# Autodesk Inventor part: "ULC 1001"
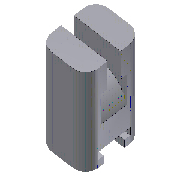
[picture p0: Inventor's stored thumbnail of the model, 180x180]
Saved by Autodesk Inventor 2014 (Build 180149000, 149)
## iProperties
Created: 2009-11
Part Number: "ULC 1001"
Material: DIN 1.2344
Description: Coupling
Document SubType Name: Modeling
Designer: gaom
Standard Revision: 1
Manufacturer: DME
Language: en-US
Size Designation: "1001"
Categories: <MemberInstance><Categories><Category DisplayName="Mold" InternalName="349578f2-f4d4-4954-8c09-8e99297a61c0" Mnemonic="MOLD"><Category DisplayName="Lifter Compo
Density: 100 g/cm^3
Appearance: Sea Green
IsCustomPart: 1
Author: gaom
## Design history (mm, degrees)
sketch "Sketch1"
  geometry: L1 (0, -9)-(0, 26) reference; L2 (0, 21)-(-11, 21); L3 (-11, 21)-(-11, -4); L4 (-11, -4)-(-4, -4); L5 (-4, -4)-(-4, -2); L6 (-4, -2)-(-6.25, -2); L7 (-6.25, -2)-(-6.25, 0); L8 (-6.25, 0)-(0, 0); L9 (11, 21)-(11, -4); L10 (0, 21)-(11, 21); L11 (11, -4)-(4, -4); L12 (4, -4)-(4, -2); L13 (4, -2)-(6.25, -2); L14 (6.25, -2)-(6.25, 0); L15 (6.25, 0)-(0, 0)
  constraints: 28 end point, 6 symmetric about line, 4 perpendicular, 3 parallel, 1 horizontal, 1 point on line
  dimensions: "d1" = 22 diameter of L3 L1 (= W_); "d2" = 25 distance between parallel lines of L4 L2 (= H_); "d3" = 12.5 diameter of L7 L1 (= ULC_ULG_W1); "d4" = 8 diameter of L5 L1 (= ULC_ULG_W2); "d5" = 4 distance between parallel lines of L4 L8 (= ULC_ULG_H1); "d6" = 2 distance between parallel lines of L4 L6 (= ULC_ULG_H2)
extrude "Extrusion1" new body sketch "Sketch1" distance "d7" = 18 (= L); taper "d8" = 0 deg
fillet "Fillet1" dims "d9" = 5 (= ULC_a1)
sketch "Sketch2"
  geometry: L1 (-18, 0)-(-18, 21) reference; L2 (-5, 21)-(-13, 21) reference; L3 (-9, 21)-(-9, -4); L4 (0, -4)-(-18, -4) reference; L5 (0, 0)-(0, 0) reference; L6 (-18, 14)-(-18, 6.359); L7 (0, 6.359)-(0, 14); L8 (0, 14)-(0, 6.359); L9 (-18, 14)-(-18, 21); L10 (-18, 21)-(0, 21); L11 (0, 21)-(0, 14); A1 r 10 centre (-9, 2) between (0, 6.359) and (-18, 6.359); A2 r 15 centre (-9, 2) between (0, 14) and (-18, 14)
  constraints: 14 end point, 5 point on line, 4 collinear, 4 point on circle, 2 centre point, 2 midpoint, 2 perpendicular, 1 coincident
  dimensions: "d10" = 10 radius of A1 (= R); "d11" = 6 distance of L3.end A1.centre (= RC); "d18" = 5 radial gap between concentric circles of A1 A2 (= ULC_ULB_H)
extrude "Extrusion2" cut sketch "Sketch2" stored distance "d19" = 10 (= ULC_ULB_Wmin); taper "d20" = 0 deg
node "ULC_ULB"
node "ULC_ULG"
body "Solid1"
extrude "Extrusion3" cut sketch "Sketch2" stored distance "d23" = 5 (= ULC_ULB_W1); taper "d24" = 0 deg
other parameters: "ULC_ULB_H" = 5 [user parameter; used in 1 equation term], "W_" = 22 [user parameter; used in 1 equation term], "L" = 18 [user parameter; used in 1 equation term], "H_" = 25 [user parameter; used in 1 equation term], "RC" = 6 [user parameter; used in 1 equation term], "R" = 10 [user parameter; used in 1 equation term], "ULC_ULB_Wmin" = 10 [user parameter; used in 1 equation term], "ULC_ULB_W1" = 5 [user parameter; used in 1 equation term], "ULC_ULG_W1" = 12.5 [user parameter; used in 1 equation term], "ULC_ULG_W2" = 8 [user parameter; used in 1 equation term], "ULC_ULG_H1" = 4 [user parameter; used in 1 equation term], "ULC_ULG_H2" = 2 [user parameter; used in 1 equation term], "d25" = 0, "ULC_a1" = 5 [user parameter; used in 1 equation term]
